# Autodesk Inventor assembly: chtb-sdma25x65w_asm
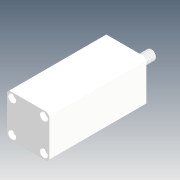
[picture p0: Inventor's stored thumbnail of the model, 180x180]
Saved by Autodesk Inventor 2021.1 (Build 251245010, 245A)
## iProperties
Company: Microsoft
Created: 2018-05
Part Number: chtb-sdma25x65w_asm
Description: STEP AP214
Document SubType Name: Assembly
Designer: user
Title: chtb-sdma25x65w_asm.STEP
Author: Windows
Revision Number: ÈÎºÎ
Sending System: SolidWorks 2015
Preprocessor: SwSTEP 2.0
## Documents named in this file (4)
- D:\Vault_2016\Projekty\Clamptek\Hydraulic\CHTB\CHTB-25\Inventor\chtb-sdma25x65w\chtb-sdma25x65w_asm.iam
- D:\Vault_2016\Projekty\Clamptek\Hydraulic\CHTB\CHTB-25\Inventor\chtb-sdma25x65w\CHTB-25QG.ipt
- D:\Vault_2016\Projekty\Clamptek\Hydraulic\CHTB\CHTB-25\Inventor\chtb-sdma25x65w\CHTB-SDMA25X65NBT.ipt
- D:\Vault_2016\Projekty\Clamptek\Hydraulic\CHTB\CHTB-25\Inventor\chtb-sdma25x65w\CHTB-SDMA25X65WHSG.ipt
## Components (3 placed, 3 different names)
1. CHTB-25QG_1
2. CHTB-SDMA25X65NBT_2
3. CHTB-SDMA25X65WHSG_3
